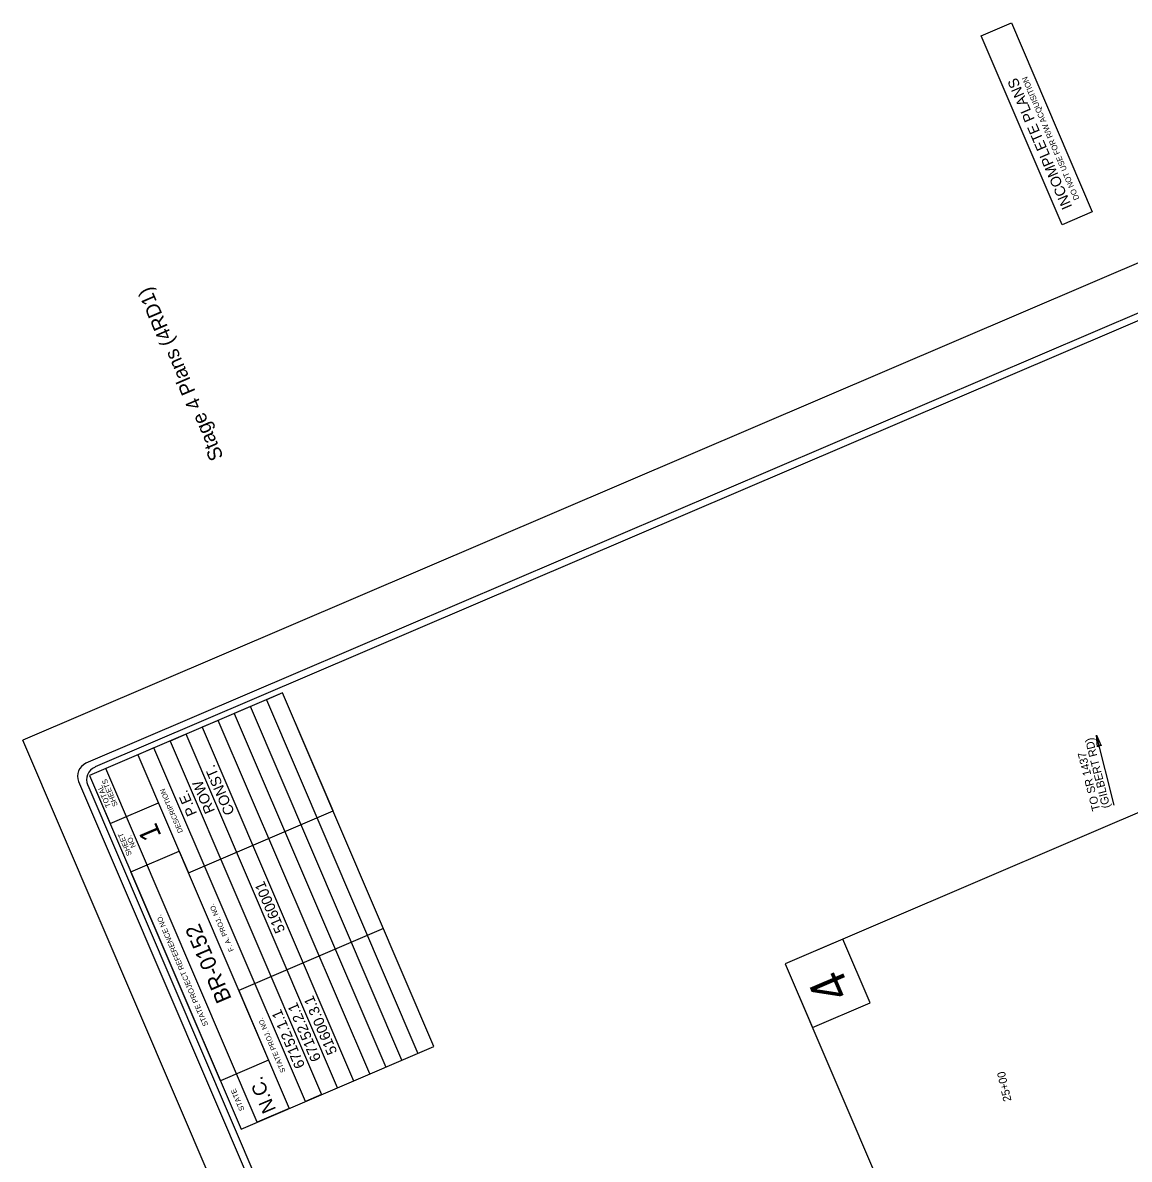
# Model space of a CAD drawing. Extents: x 1550250 to 1553210, y 808906 to 812497.
# Drawn here: x 1550250 to 1551614, y 811095 to 812497 of the extents above; entities that cross this region are included whole.
import ezdxf

# ---------------------------------------------------------------- set-up
doc = ezdxf.new("R2010")
doc.units = 0
for name, color, linetype in [('P_RDY_DSN_Text', 7, 'Continuous'), ('Prop DSN Text', 7, 'Continuous'), ('Prop Terminator Cell', 7, 'Continuous'), ('Scratch_Level_0', 7, 'Continuous'), ('Sheet_Data_Field_CELL', 7, 'Continuous'), ('Sheet_Plan_CELL', 7, 'Continuous'), ('Sheet_Sticker_Incomplete_CELL', 7, 'Continuous'), ('Sheet_Title_CELL', 7, 'Continuous')]:
    doc.layers.add(name, color=color, linetype=linetype)

msp = doc.modelspace()

# ---------------------------------------------------------------- linework, layer by layer
at = {"layer": 'Prop DSN Text'}
msp.add_line((1551595.8, 811531.8), (1551573.9, 811618.1), dxfattribs=at)
at = {"layer": 'Prop Terminator Cell'}
msp.add_lwpolyline([(1551575, 811603.5), (1551573.9, 811618.1), (1551579.9, 811604.7), (1551577, 811605.8)], close=True, dxfattribs=at)
at = {"layer": 'Scratch_Level_0'}
for p in [(1551994.4, 812358.6), (1551404, 808916)]:
    msp.add_line(p, (1550250, 811611.9), dxfattribs=at)
at = {"layer": 'Sheet_Plan_CELL'}
for points in [[(1551190.2, 811336.1), (1551800.2, 809911.1), (1552391.4, 810164.1), (1551781.4, 811589.2)], [(1551190.2, 811336.1), (1551223.9, 811257.4), (1551295, 811287.9), (1551261.3, 811366.6)]]:
    msp.add_lwpolyline(points, close=True, dxfattribs=at)
at = {"layer": 'Sheet_Sticker_Incomplete_CELL'}
for p, q in [((1551431.8, 812480.6), (1551469, 812496.6)), ((1551469, 812496.6), (1551568.8, 812263.5)), ((1551531.6, 812247.5), (1551431.8, 812480.6)), ((1551568.8, 812263.5), (1551531.6, 812247.5))]:
    msp.add_line(p, q, dxfattribs=at)
at = {"layer": 'Sheet_Title_CELL'}
for p, q in [((1550570.4, 811670.2), (1550332.5, 811568.4)), ((1550570.4, 811670.2), (1550550.6, 811661.8)), ((1550550.6, 811661.8), (1550737.2, 811225.6)), ((1550757.1, 811234.1), (1550570.4, 811670.2)), ((1550632.6, 811524.8), (1550570.4, 811670.2)), ((1550530.8, 811653.3), (1550510.9, 811644.8)), ((1550510.9, 811644.8), (1550697.6, 811208.7)), ((1550717.4, 811217.2), (1550530.8, 811653.3)), ((1550491.1, 811636.3), (1550471.3, 811627.8)), ((1550677.8, 811200.2), (1550491.1, 811636.3)), ((1550451.5, 811619.3), (1550431.7, 811610.8)), ((1550638.2, 811183.2), (1550451.5, 811619.3)), ((1550471.3, 811627.8), (1550658, 811191.7)), ((1550411.8, 811602.4), (1550392, 811593.9)), ((1550598.5, 811166.3), (1550411.8, 811602.4)), ((1550431.7, 811610.8), (1550618.3, 811174.7)), ((1550392, 811593.9), (1550578.7, 811157.8)), ((1550352.3, 811576.9), (1550332.5, 811568.4)), ((1550539, 811140.8), (1550352.3, 811576.9)), ((1550318.9, 811560.7), (1551421.3, 808985.4)), ((1550332.5, 811568.4), (1550519.2, 811132.3)), ((1550332.5, 811568.4), (1550358, 811508.9)), ((1550330.3, 811556.2), (1551391.9, 809076.1)), ((1550358, 811508.9), (1550417.4, 811534.4)), ((1550454.2, 811448.4), (1550632.6, 811524.8)), ((1550383.4, 811449.5), (1550442.9, 811474.9)), ((1550442.9, 811474.9), (1550454.2, 811448.4)), ((1550493.7, 811191.8), (1550383.4, 811449.5)), ((1550694.9, 811379.5), (1550516.5, 811303.1)), ((1550516.5, 811303.1), (1550553.2, 811217.2)), ((1550519.2, 811132.3), (1550757.1, 811234.1)), ((1550553.2, 811217.2), (1550493.7, 811191.8)), ((1550618.3, 811174.7), (1550598.5, 811166.3)), ((1550578.7, 811157.8), (1550539, 811140.8))]:
    msp.add_line(p, q, dxfattribs=at)
for points in [[(1551961.4, 812282.5), (1550328, 811583.4)], [(1551663.5, 812145.6), (1550339.3, 811578.8)]]:
    msp.add_lwpolyline(points, dxfattribs=at)
for centre in [(1550334.7, 811567.5), (1550346, 811562.9)]:
    msp.add_arc(centre, 17.2, 113.1736, 203.1736, dxfattribs=at)

# ---------------------------------------------------------------- texts
at = {"layer": 'P_RDY_DSN_Text'}
for s, height, rotation, p in [('4', 45, 113.1736, (1551272, 811300.4)), ('25+00', 10, 102.7833, (1551469.2, 811167.4))]:
    msp.add_text(s, height=height, rotation=rotation, dxfattribs=at).set_placement(p)
at = {"layer": 'Prop DSN Text'}
for s, height, rotation, p in [('Stage 4 Plans (4RD1)', 17.664, 113.1736, (1550497.9, 811961)), ('(GILBERT RD)', 10, 104.262, (1551591.1, 811529.2)), ('TO SR 1437', 10, 104.262, (1551578.6, 811526))]:
    msp.add_text(s, height=height, rotation=rotation, dxfattribs=at).set_placement(p)
at = {"layer": 'Sheet_Data_Field_CELL'}
for s, height, p in [('CONST.', 12.94, (1550511.6, 811522.7)), ('ROW', 12.94, (1550487.3, 811524.7)), ('P.E.', 12.94, (1550465.2, 811521.5)), ('5160001', 12.94, (1550573.9, 811377.2)), ('BR-0152', 19.41, (1550507.9, 811292.9)), ('51600.3.1', 12.94, (1550638.1, 811227.3)), ('67152.1.1', 12.94, (1550598.4, 811210.3)), ('67152.2.1', 12.94, (1550618.2, 811218.8))]:
    msp.add_text(s, height=height, rotation=113.1736, dxfattribs=at).set_placement(p)
at = {"layer": 'Sheet_Sticker_Incomplete_CELL'}
for s, height, p in [('DO NOT USE FOR R/W ACQUISITION', 6.986, (1551553, 812279.6)), ('INCOMPLETE PLANS', 12.938, (1551544.2, 812269.7))]:
    msp.add_text(s, height=height, rotation=113.1736, dxfattribs=at).set_placement(p)
at = {"layer": 'Sheet_Title_CELL'}
for s, height, p in [('SHEETS', 6.47, (1550367.4, 811531.7)), ('TOTAL', 6.47, (1550358.9, 811530.5)), ('DESCRIPTION', 6.21, (1550447.7, 811499)), ('1', 25, (1550421.4, 811494.2)), ('SHEET', 6.47, (1550384.7, 811470.9)), ('NO.', 6.47, (1550389.7, 811480.7)), ('F. A. PROJ. NO.', 6.21, (1550510.4, 811352.6)), ('STATE PROJECT REFERENCE NO.', 6.468, (1550478.9, 811260.6)), ('STATE PROJ. NO.', 6.21, (1550574.2, 811203.4)), ('N.C.', 17.25, (1550562.6, 811156.3)), ('STATE', 6.47, (1550523.6, 811156.3))]:
    msp.add_text(s, height=height, rotation=113.1736, dxfattribs=at).set_placement(p)

doc.saveas('drawing.dxf')
